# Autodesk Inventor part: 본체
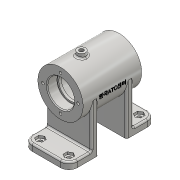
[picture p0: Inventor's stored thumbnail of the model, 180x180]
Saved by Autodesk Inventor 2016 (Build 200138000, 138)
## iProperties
Created: 2017-02
Part Number: 본체
Material: 알루미늄 6061
Document SubType Name: Modeling
Designer: H
Density: 2.7 g/cm^3
Appearance: 알루미늄 - 평지
Mass: 368.505 g
Surface Area: 420.473 cm^2
Volume: 136.483 cm^3
Author: H
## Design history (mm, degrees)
sketch "스케치1"
  geometry: C1 r 27 at (0, 0); 1 further point
  constraints: 1 centre point, 1 coincident
  dimensions: "d0" = 54 diameter of C1
extrude "돌출1" new body sketch "스케치1" stored distance "d1" = 70; taper "d2" = 0 deg
node "작업 평면2"
  node "작업 평면1"
sketch "스케치2"
  geometry: L1 (0, -27)-(0, 27) reference; L2 (-70, 27)-(-70, -27) reference; L3 (-35, 0)-(-35, 69.271); L4 (-87, -27)-(-52, -27); L5 (-52, -27)-(-52, 27); L6 (-52, 27)-(-87, 27); L7 (-87, 27)-(-87, -27); L8 (17, 27)-(17, -27); L9 (17, -27)-(-18, -27); L10 (-18, 27)-(17, 27); L11 (-18, -27)-(-18, 27); 2 further points
  constraints: 18 end point, 4 symmetric about line, 2 midpoint, 2 parallel, 1 horizontal, 1 horizontal alignment, 1 perpendicular, 1 vertical
  dimensions: "d5" = 54 distance of L6.end L4.start; "d6" = 104 diameter of L7 L3; "d7" = 34 diameter of L5 L3
extrude "돌출2" join sketch "스케치2" distance "d8" = 8; taper "d9" = 0 deg
sketch "스케치4"
  geometry: L1 (0, 0)-(0, -78.007); L2 (-17, -60)-(-17, -52) reference; L3 (-17, -52)-(-52, -52) reference; L4 (-17, -60)-(-52, -60) reference; L5 (-52, -60)-(-52, -52) reference; L6 (-17, -52)-(-52, -52) reference; L7 (-17, -60)-(-17, -52) reference; L8 (-17, -60)-(-25, -60); L9 (-25, -60)-(-25, 0); L10 (-25, 0)-(-17, 0); L11 (-17, 0)-(-17, -60); L12 (25, 0)-(17, 0); L13 (17, 0)-(17, -60); L14 (25, -60)-(25, 0); L15 (17, -60)-(25, -60)
  constraints: 18 end point, 4 symmetric about line, 2 horizontal, 2 parallel, 1 perpendicular, 1 vertical
  dimensions: "d10" = 8 distance of L9.end L10.end; "d11" = 60 distance of L8.end L9.end
extrude "돌출3" join sketch "스케치4" stored distance "d12" = 54; taper "d13" = 0 deg
node "작업 평면3"
sketch "스케치5"
  geometry: L1 (0, 0)-(0, 50.633); L2 (-5, 32)-(0, 32); L3 (0, 32)-(0, 22); L4 (0, 22)-(-5, 22); L5 (-5, 22)-(-5, 32); L6 (-27, -60)-(27, -60) reference
  constraints: 10 end point, 2 parallel, 1 horizontal, 1 perpendicular, 1 point on line, 1 vertical
  dimensions: "d15" = 92 distance between parallel lines of L6 L2; "d16" = 5 distance of L2.start L2.end; "d17" = 10 distance of L4.end L2.start
revolve "회전1" sketch "스케치5" stored, may be unused: angle "d18" = 90 deg
sketch "스케치8"
  geometry: L1 (-46.083, 0)-(65.463, 0); L2 (-35, 27)-(35, 27) reference; L3 (-35, 27)-(-35, -27) reference; L4 (-35, 0)-(-35, 16); L5 (-35, 16)-(-23, 16); L6 (-23, 16)-(-23, 14); L7 (-23, 14)-(-20, 14); L8 (-20, 14)-(-20, 21); L9 (-20, 21)-(20, 21); L10 (20, 21)-(20, 14); L11 (20, 14)-(23, 14); L12 (23, 14)-(23, 16); L13 (23, 16)-(35, 16); L14 (35, 16)-(35, 0); L15 (35, 0)-(-35, 0); 1 further point
  constraints: 26 end point, 10 perpendicular, 2 point on line, 1 horizontal, 1 midpoint
  dimensions: "d19" = 27 distance between parallel lines of L1 L2; "d20" = 16 distance of L4.start L4.end; "d21" = 12 distance of L4.end L5.end; "d22" = 3 distance of L6.end L7.end; "d23" = 40 distance of L8.end L9.end; "d24" = 3 distance of L10.end L11.end; "d25" = 12 distance of L12.end L13.end; "d26" = 14 distance between parallel lines of L1 L7; "d27" = 21 distance from line of L4.start L9; "d28" = 14 distance between parallel lines of L1 L11; "d29" = 16 distance between parallel lines of L1 L13
revolve "회전2" sketch "스케치8" stored, may be unused: angle "d30" = 90 deg
sketch "스케치9"
  geometry: C1 r 5 at (0, 0) reference; 2 further points
  constraints: 1 coincident
hole "구멍1" sketch "스케치9" at (0, 0) diameter "d31" = 5.188; stored, may be unused: countersink angle "d35" = 90 deg, drill point angle "d37" = 118 deg; dims "d32" = 12, "d33" = 4, "d34" = 2, "d36" = 16
sketch "스케치10"
  geometry: L1 (0, 0)-(0, 22.88); C1 r 27 at (0, 0) reference; 2 further points
  constraints: 2 end point, 1 point on line, 1 vertical
  dimensions: "d38" = 21 distance of point (0, 0) point (0, 21)
hole "구멍2" sketch "스케치10" at (0, 21) diameter "d39" = 3.242; stored, may be unused: countersink angle "d43" = 90 deg, drill point angle "d45" = 118 deg; dims "d40" = 8, "d41" = 4, "d42" = 2, "d44" = 10
sketch "스케치11"
  geometry: L1 (0, 0)-(25.302, -38.962); L2 (0, 0)-(0, -74.186); L3 (18.648, -17.699)-(21.371, -21.892); L4 (21.371, -21.892)-(16.339, -25.16); L5 (18.648, -17.699)-(13.616, -20.967); L6 (13.616, -20.967)-(16.339, -25.16)
  constraints: 12 end point, 2 perpendicular, 2 point on line, 1 parallel, 1 vertical
  dimensions: "d49" = 33 deg angle of L2 L1; "d50" = 6 distance of L3.end L4.end; "d51" = 30 distance from line of L1.start L4; "d52" = 5 distance of L3.start L3.end
revolve "회전3" sketch "스케치11" stored, may be unused: angle "d53" = 90 deg
sketch "스케치12"
  geometry: C1 r 6 at (0, 0) reference; 2 further points
  constraints: 1 coincident
sketch "스케치13"
  geometry: L1 (-87, 17)-(-87, 87) reference; L2 (-87, 17)-(-33, 17) reference; 2 further points
  constraints: 1 other
  dimensions: "d54" = 35 distance from line of point (-60, 52) L2; "d55" = 27 distance from line of point (-60, 52) L1
feature "엠보싱1" sketch "스케치13" dims "d56" = 0.5, "d57" = 0
chamfer "모따기1" distance "d58" = 1; stored, may be unused: second distance "d59" = 2, angle "d60" = 45 deg
fillet "모깎기1" dims "d61" = 0.3
fillet "모깎기2" dims "d62" = 3
sketch "스케치14"
  geometry: L1 (-27, 60)-(27, 60) reference; L2 (27, 60)-(27, 87) reference; L3 (27, 87)-(-27, 87) reference; L4 (-27, 87)-(-27, 60) reference; L5 (0, 87)-(0, 67.297); L6 (0, 35)-(67.583, 35); L7 (-17, 82.196)-(-12.5, 79.598); L8 (-12.5, 79.598)-(-12.5, 74.402); L9 (-12.5, 74.402)-(-17, 71.804); L10 (-17, 71.804)-(-21.5, 74.402); L11 (-21.5, 74.402)-(-21.5, 79.598); L12 (-21.5, 79.598)-(-17, 82.196); L13 (-17, 77)-(-17, 71.133); C1 r 4.5 at (-17, 77); 1 further point
  constraints: 18 end point, 2 coincident, 2 vertical, 1 centre point, 1 horizontal, 1 midpoint, 1 point on line, 1 tangent, 13 other
  dimensions: "d63" = 34 diameter of point (-17, 77) L5; "d64" = 84 diameter of point (-17, 77) L6; "d65" = 9 diameter of C1
extrude "돌출4" cut sketch "스케치14" distance "d66" = 3; taper "d67" = 0 deg
sketch "스케치16"
  geometry: L1 (27, 87)-(-27, 87) reference; L2 (-27, 87)-(-27, 60) reference; 2 further points
  dimensions: "d68" = 10 distance from line of point (-17, 77) L1; "d69" = 10 distance from line of L2 point (-17, 77)
hole "구멍3" sketch "스케치16" at (-17, 77) diameter "d70" = 5; stored, may be unused: countersink angle "d74" = 90 deg, drill point angle "d76" = 118 deg; dims "d71" = 12, "d72" = 10, "d73" = 3, "d75" = 16
fillet "모깎기3" dims "d83" = 10
fillet "모깎기4" dims "d84" = 2
fillet "모깎기5" dims "d85" = 2
fillet "모깎기6" dims "d86" = 2
hole "구멍4" sketch "스케치12" diameter "d87" = 5.188; stored, may be unused: countersink angle "d91" = 90 deg, drill point angle "d93" = 118 deg; dims "d88" = 12, "d89" = 10, "d90" = 3, "d92" = 16
node "솔리드1"
pattern_circular "원형 패턴1" dims angle "d47" = 360 deg
mirror "대칭1"
pattern_linear "직사각형 패턴1" dims "d79" = 34, "d82" = 84
node "작업축1"
node "투영된 루프1"
node "투영된 루프2"
node "투영된 루프3"
other parameters: "d3" = 0, "d14" = -25
